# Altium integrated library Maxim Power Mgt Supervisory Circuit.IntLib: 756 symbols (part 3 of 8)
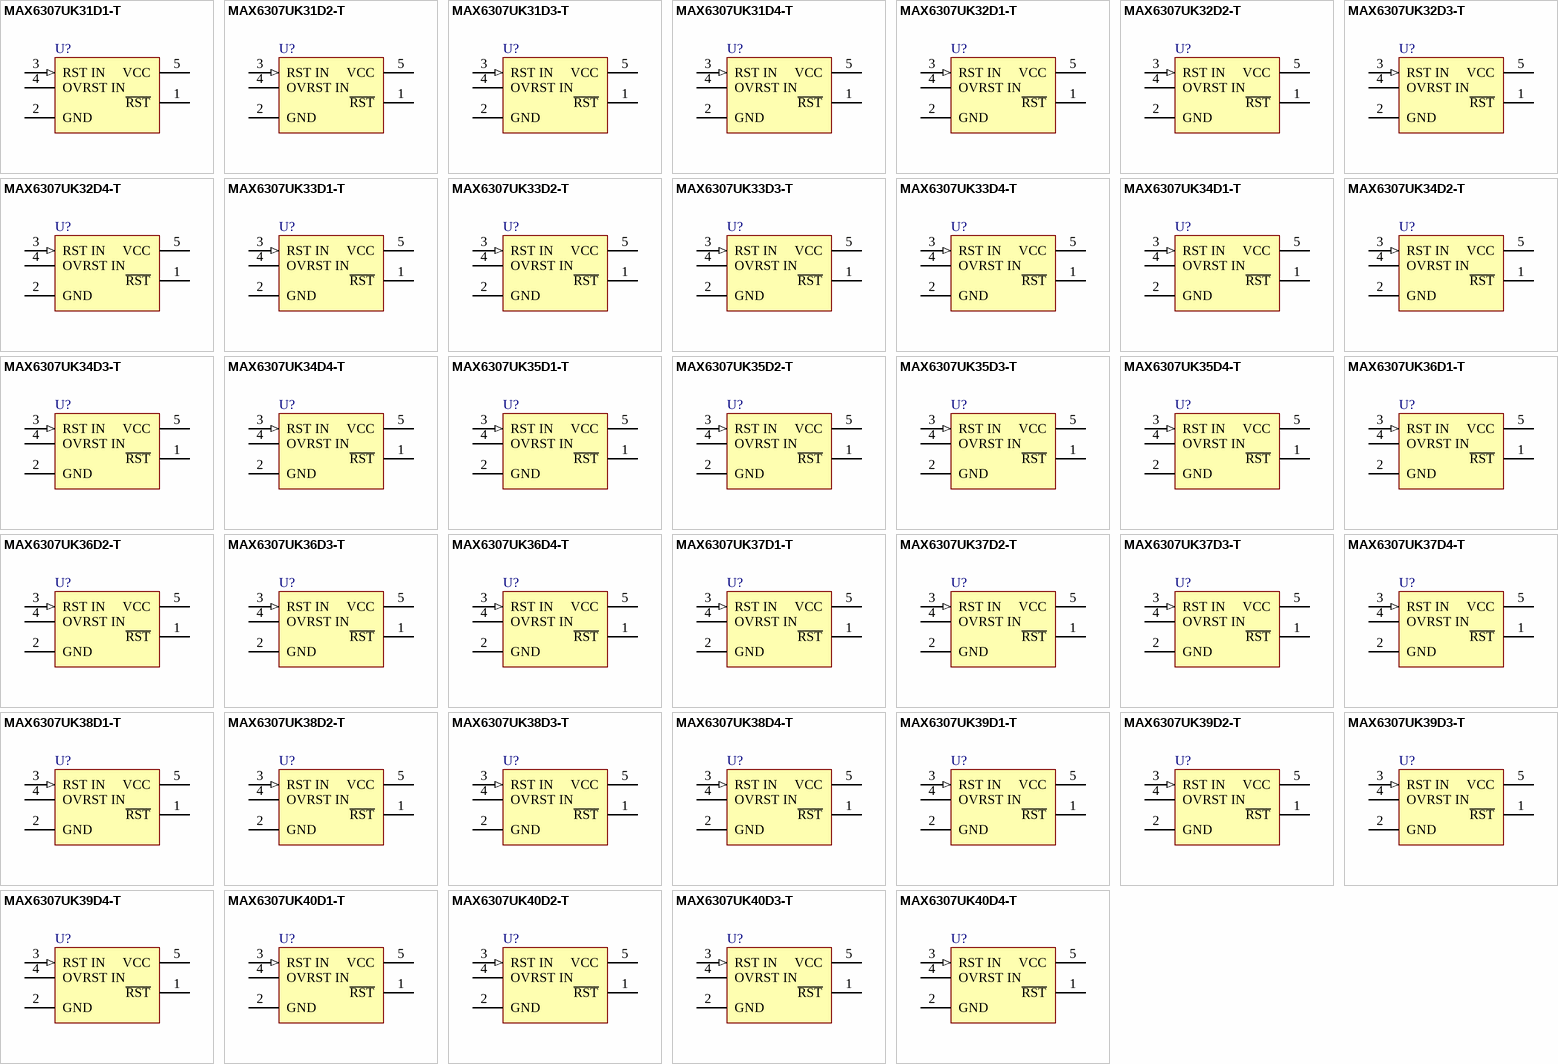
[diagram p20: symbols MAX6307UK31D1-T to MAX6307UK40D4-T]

## MAX6307UK35D3-T
designator U?
5-Pin, Multiple-Input, Programmable Reset IC
footprint SOT23-5_N (SOT23, 5-Leads, Body 2.9x1.6mm, Pitch 0.95mm, Lead Span 2.8mm, IPC Medium Density)
footprint SOT23-5_L (SOT23, 5-Leads, Body 2.9x1.6mm, Pitch 0.95mm, Lead Span 2.8mm, IPC High Density)
footprint SOT23-5_M (SOT23, 5-Leads, Body 2.9x1.6mm, Pitch 0.95mm, Lead Span 2.8mm, IPC Low Density)
pins: 1 ~{RST} (oc), 2 GND (power), 3 RST IN (in), 4 OVRST IN, 5 VCC (power)

## MAX6307UK35D4-T
designator U?
5-Pin, Multiple-Input, Programmable Reset IC
footprint SOT23-5_N (SOT23, 5-Leads, Body 2.9x1.6mm, Pitch 0.95mm, Lead Span 2.8mm, IPC Medium Density)
footprint SOT23-5_L (SOT23, 5-Leads, Body 2.9x1.6mm, Pitch 0.95mm, Lead Span 2.8mm, IPC High Density)
footprint SOT23-5_M (SOT23, 5-Leads, Body 2.9x1.6mm, Pitch 0.95mm, Lead Span 2.8mm, IPC Low Density)
pins: 1 ~{RST} (oc), 2 GND (power), 3 RST IN (in), 4 OVRST IN, 5 VCC (power)

## MAX6307UK36D1-T
designator U?
5-Pin, Multiple-Input, Programmable Reset IC
footprint SOT23-5_N (SOT23, 5-Leads, Body 2.9x1.6mm, Pitch 0.95mm, Lead Span 2.8mm, IPC Medium Density)
footprint SOT23-5_L (SOT23, 5-Leads, Body 2.9x1.6mm, Pitch 0.95mm, Lead Span 2.8mm, IPC High Density)
footprint SOT23-5_M (SOT23, 5-Leads, Body 2.9x1.6mm, Pitch 0.95mm, Lead Span 2.8mm, IPC Low Density)
pins: 1 ~{RST} (oc), 2 GND (power), 3 RST IN (in), 4 OVRST IN, 5 VCC (power)

## MAX6307UK36D2-T
designator U?
5-Pin, Multiple-Input, Programmable Reset IC
footprint SOT23-5_N (SOT23, 5-Leads, Body 2.9x1.6mm, Pitch 0.95mm, Lead Span 2.8mm, IPC Medium Density)
footprint SOT23-5_L (SOT23, 5-Leads, Body 2.9x1.6mm, Pitch 0.95mm, Lead Span 2.8mm, IPC High Density)
footprint SOT23-5_M (SOT23, 5-Leads, Body 2.9x1.6mm, Pitch 0.95mm, Lead Span 2.8mm, IPC Low Density)
pins: 1 ~{RST} (oc), 2 GND (power), 3 RST IN (in), 4 OVRST IN, 5 VCC (power)

## MAX6307UK36D3-T
designator U?
5-Pin, Multiple-Input, Programmable Reset IC
footprint SOT23-5_N (SOT23, 5-Leads, Body 2.9x1.6mm, Pitch 0.95mm, Lead Span 2.8mm, IPC Medium Density)
footprint SOT23-5_L (SOT23, 5-Leads, Body 2.9x1.6mm, Pitch 0.95mm, Lead Span 2.8mm, IPC High Density)
footprint SOT23-5_M (SOT23, 5-Leads, Body 2.9x1.6mm, Pitch 0.95mm, Lead Span 2.8mm, IPC Low Density)
pins: 1 ~{RST} (oc), 2 GND (power), 3 RST IN (in), 4 OVRST IN, 5 VCC (power)

## MAX6307UK36D4-T
designator U?
5-Pin, Multiple-Input, Programmable Reset IC
footprint SOT23-5_N (SOT23, 5-Leads, Body 2.9x1.6mm, Pitch 0.95mm, Lead Span 2.8mm, IPC Medium Density)
footprint SOT23-5_L (SOT23, 5-Leads, Body 2.9x1.6mm, Pitch 0.95mm, Lead Span 2.8mm, IPC High Density)
footprint SOT23-5_M (SOT23, 5-Leads, Body 2.9x1.6mm, Pitch 0.95mm, Lead Span 2.8mm, IPC Low Density)
pins: 1 ~{RST} (oc), 2 GND (power), 3 RST IN (in), 4 OVRST IN, 5 VCC (power)

## MAX6307UK37D1-T
designator U?
5-Pin, Multiple-Input, Programmable Reset IC
footprint SOT23-5_N (SOT23, 5-Leads, Body 2.9x1.6mm, Pitch 0.95mm, Lead Span 2.8mm, IPC Medium Density)
footprint SOT23-5_L (SOT23, 5-Leads, Body 2.9x1.6mm, Pitch 0.95mm, Lead Span 2.8mm, IPC High Density)
footprint SOT23-5_M (SOT23, 5-Leads, Body 2.9x1.6mm, Pitch 0.95mm, Lead Span 2.8mm, IPC Low Density)
pins: 1 ~{RST} (oc), 2 GND (power), 3 RST IN (in), 4 OVRST IN, 5 VCC (power)

## MAX6307UK37D2-T
designator U?
5-Pin, Multiple-Input, Programmable Reset IC
footprint SOT23-5_N (SOT23, 5-Leads, Body 2.9x1.6mm, Pitch 0.95mm, Lead Span 2.8mm, IPC Medium Density)
footprint SOT23-5_L (SOT23, 5-Leads, Body 2.9x1.6mm, Pitch 0.95mm, Lead Span 2.8mm, IPC High Density)
footprint SOT23-5_M (SOT23, 5-Leads, Body 2.9x1.6mm, Pitch 0.95mm, Lead Span 2.8mm, IPC Low Density)
pins: 1 ~{RST} (oc), 2 GND (power), 3 RST IN (in), 4 OVRST IN, 5 VCC (power)

## MAX6307UK37D3-T
designator U?
5-Pin, Multiple-Input, Programmable Reset IC
footprint SOT23-5_N (SOT23, 5-Leads, Body 2.9x1.6mm, Pitch 0.95mm, Lead Span 2.8mm, IPC Medium Density)
footprint SOT23-5_L (SOT23, 5-Leads, Body 2.9x1.6mm, Pitch 0.95mm, Lead Span 2.8mm, IPC High Density)
footprint SOT23-5_M (SOT23, 5-Leads, Body 2.9x1.6mm, Pitch 0.95mm, Lead Span 2.8mm, IPC Low Density)
pins: 1 ~{RST} (oc), 2 GND (power), 3 RST IN (in), 4 OVRST IN, 5 VCC (power)

## MAX6307UK37D4-T
designator U?
5-Pin, Multiple-Input, Programmable Reset IC
footprint SOT23-5_N (SOT23, 5-Leads, Body 2.9x1.6mm, Pitch 0.95mm, Lead Span 2.8mm, IPC Medium Density)
footprint SOT23-5_L (SOT23, 5-Leads, Body 2.9x1.6mm, Pitch 0.95mm, Lead Span 2.8mm, IPC High Density)
footprint SOT23-5_M (SOT23, 5-Leads, Body 2.9x1.6mm, Pitch 0.95mm, Lead Span 2.8mm, IPC Low Density)
pins: 1 ~{RST} (oc), 2 GND (power), 3 RST IN (in), 4 OVRST IN, 5 VCC (power)

## MAX6307UK38D1-T
designator U?
5-Pin, Multiple-Input, Programmable Reset IC
footprint SOT23-5_N (SOT23, 5-Leads, Body 2.9x1.6mm, Pitch 0.95mm, Lead Span 2.8mm, IPC Medium Density)
footprint SOT23-5_L (SOT23, 5-Leads, Body 2.9x1.6mm, Pitch 0.95mm, Lead Span 2.8mm, IPC High Density)
footprint SOT23-5_M (SOT23, 5-Leads, Body 2.9x1.6mm, Pitch 0.95mm, Lead Span 2.8mm, IPC Low Density)
pins: 1 ~{RST} (oc), 2 GND (power), 3 RST IN (in), 4 OVRST IN, 5 VCC (power)

## MAX6307UK38D2-T
designator U?
5-Pin, Multiple-Input, Programmable Reset IC
footprint SOT23-5_N (SOT23, 5-Leads, Body 2.9x1.6mm, Pitch 0.95mm, Lead Span 2.8mm, IPC Medium Density)
footprint SOT23-5_L (SOT23, 5-Leads, Body 2.9x1.6mm, Pitch 0.95mm, Lead Span 2.8mm, IPC High Density)
footprint SOT23-5_M (SOT23, 5-Leads, Body 2.9x1.6mm, Pitch 0.95mm, Lead Span 2.8mm, IPC Low Density)
pins: 1 ~{RST} (oc), 2 GND (power), 3 RST IN (in), 4 OVRST IN, 5 VCC (power)

## MAX6307UK38D3-T
designator U?
5-Pin, Multiple-Input, Programmable Reset IC
footprint SOT23-5_N (SOT23, 5-Leads, Body 2.9x1.6mm, Pitch 0.95mm, Lead Span 2.8mm, IPC Medium Density)
footprint SOT23-5_L (SOT23, 5-Leads, Body 2.9x1.6mm, Pitch 0.95mm, Lead Span 2.8mm, IPC High Density)
footprint SOT23-5_M (SOT23, 5-Leads, Body 2.9x1.6mm, Pitch 0.95mm, Lead Span 2.8mm, IPC Low Density)
pins: 1 ~{RST} (oc), 2 GND (power), 3 RST IN (in), 4 OVRST IN, 5 VCC (power)

## MAX6307UK38D4-T
designator U?
5-Pin, Multiple-Input, Programmable Reset IC
footprint SOT23-5_N (SOT23, 5-Leads, Body 2.9x1.6mm, Pitch 0.95mm, Lead Span 2.8mm, IPC Medium Density)
footprint SOT23-5_L (SOT23, 5-Leads, Body 2.9x1.6mm, Pitch 0.95mm, Lead Span 2.8mm, IPC High Density)
footprint SOT23-5_M (SOT23, 5-Leads, Body 2.9x1.6mm, Pitch 0.95mm, Lead Span 2.8mm, IPC Low Density)
pins: 1 ~{RST} (oc), 2 GND (power), 3 RST IN (in), 4 OVRST IN, 5 VCC (power)

## MAX6307UK39D1-T
designator U?
5-Pin, Multiple-Input, Programmable Reset IC
footprint SOT23-5_N (SOT23, 5-Leads, Body 2.9x1.6mm, Pitch 0.95mm, Lead Span 2.8mm, IPC Medium Density)
footprint SOT23-5_L (SOT23, 5-Leads, Body 2.9x1.6mm, Pitch 0.95mm, Lead Span 2.8mm, IPC High Density)
footprint SOT23-5_M (SOT23, 5-Leads, Body 2.9x1.6mm, Pitch 0.95mm, Lead Span 2.8mm, IPC Low Density)
pins: 1 ~{RST} (oc), 2 GND (power), 3 RST IN (in), 4 OVRST IN, 5 VCC (power)

## MAX6307UK39D2-T
designator U?
5-Pin, Multiple-Input, Programmable Reset IC
footprint SOT23-5_N (SOT23, 5-Leads, Body 2.9x1.6mm, Pitch 0.95mm, Lead Span 2.8mm, IPC Medium Density)
footprint SOT23-5_L (SOT23, 5-Leads, Body 2.9x1.6mm, Pitch 0.95mm, Lead Span 2.8mm, IPC High Density)
footprint SOT23-5_M (SOT23, 5-Leads, Body 2.9x1.6mm, Pitch 0.95mm, Lead Span 2.8mm, IPC Low Density)
pins: 1 ~{RST} (oc), 2 GND (power), 3 RST IN (in), 4 OVRST IN, 5 VCC (power)

## MAX6307UK39D3-T
designator U?
5-Pin, Multiple-Input, Programmable Reset IC
footprint SOT23-5_N (SOT23, 5-Leads, Body 2.9x1.6mm, Pitch 0.95mm, Lead Span 2.8mm, IPC Medium Density)
footprint SOT23-5_L (SOT23, 5-Leads, Body 2.9x1.6mm, Pitch 0.95mm, Lead Span 2.8mm, IPC High Density)
footprint SOT23-5_M (SOT23, 5-Leads, Body 2.9x1.6mm, Pitch 0.95mm, Lead Span 2.8mm, IPC Low Density)
pins: 1 ~{RST} (oc), 2 GND (power), 3 RST IN (in), 4 OVRST IN, 5 VCC (power)

## MAX6307UK39D4-T
designator U?
5-Pin, Multiple-Input, Programmable Reset IC
footprint SOT23-5_N (SOT23, 5-Leads, Body 2.9x1.6mm, Pitch 0.95mm, Lead Span 2.8mm, IPC Medium Density)
footprint SOT23-5_L (SOT23, 5-Leads, Body 2.9x1.6mm, Pitch 0.95mm, Lead Span 2.8mm, IPC High Density)
footprint SOT23-5_M (SOT23, 5-Leads, Body 2.9x1.6mm, Pitch 0.95mm, Lead Span 2.8mm, IPC Low Density)
pins: 1 ~{RST} (oc), 2 GND (power), 3 RST IN (in), 4 OVRST IN, 5 VCC (power)

## MAX6307UK40D1-T
designator U?
5-Pin, Multiple-Input, Programmable Reset IC
footprint SOT23-5_N (SOT23, 5-Leads, Body 2.9x1.6mm, Pitch 0.95mm, Lead Span 2.8mm, IPC Medium Density)
footprint SOT23-5_L (SOT23, 5-Leads, Body 2.9x1.6mm, Pitch 0.95mm, Lead Span 2.8mm, IPC High Density)
footprint SOT23-5_M (SOT23, 5-Leads, Body 2.9x1.6mm, Pitch 0.95mm, Lead Span 2.8mm, IPC Low Density)
pins: 1 ~{RST} (oc), 2 GND (power), 3 RST IN (in), 4 OVRST IN, 5 VCC (power)

## MAX6307UK40D2-T
designator U?
5-Pin, Multiple-Input, Programmable Reset IC
footprint SOT23-5_N (SOT23, 5-Leads, Body 2.9x1.6mm, Pitch 0.95mm, Lead Span 2.8mm, IPC Medium Density)
footprint SOT23-5_L (SOT23, 5-Leads, Body 2.9x1.6mm, Pitch 0.95mm, Lead Span 2.8mm, IPC High Density)
footprint SOT23-5_M (SOT23, 5-Leads, Body 2.9x1.6mm, Pitch 0.95mm, Lead Span 2.8mm, IPC Low Density)
pins: 1 ~{RST} (oc), 2 GND (power), 3 RST IN (in), 4 OVRST IN, 5 VCC (power)

## MAX6307UK40D3-T
designator U?
5-Pin, Multiple-Input, Programmable Reset IC
footprint SOT23-5_N (SOT23, 5-Leads, Body 2.9x1.6mm, Pitch 0.95mm, Lead Span 2.8mm, IPC Medium Density)
footprint SOT23-5_L (SOT23, 5-Leads, Body 2.9x1.6mm, Pitch 0.95mm, Lead Span 2.8mm, IPC High Density)
footprint SOT23-5_M (SOT23, 5-Leads, Body 2.9x1.6mm, Pitch 0.95mm, Lead Span 2.8mm, IPC Low Density)
pins: 1 ~{RST} (oc), 2 GND (power), 3 RST IN (in), 4 OVRST IN, 5 VCC (power)

## MAX6307UK40D4-T
designator U?
5-Pin, Multiple-Input, Programmable Reset IC
footprint SOT23-5_N (SOT23, 5-Leads, Body 2.9x1.6mm, Pitch 0.95mm, Lead Span 2.8mm, IPC Medium Density)
footprint SOT23-5_L (SOT23, 5-Leads, Body 2.9x1.6mm, Pitch 0.95mm, Lead Span 2.8mm, IPC High Density)
footprint SOT23-5_M (SOT23, 5-Leads, Body 2.9x1.6mm, Pitch 0.95mm, Lead Span 2.8mm, IPC Low Density)
pins: 1 ~{RST} (oc), 2 GND (power), 3 RST IN (in), 4 OVRST IN, 5 VCC (power)

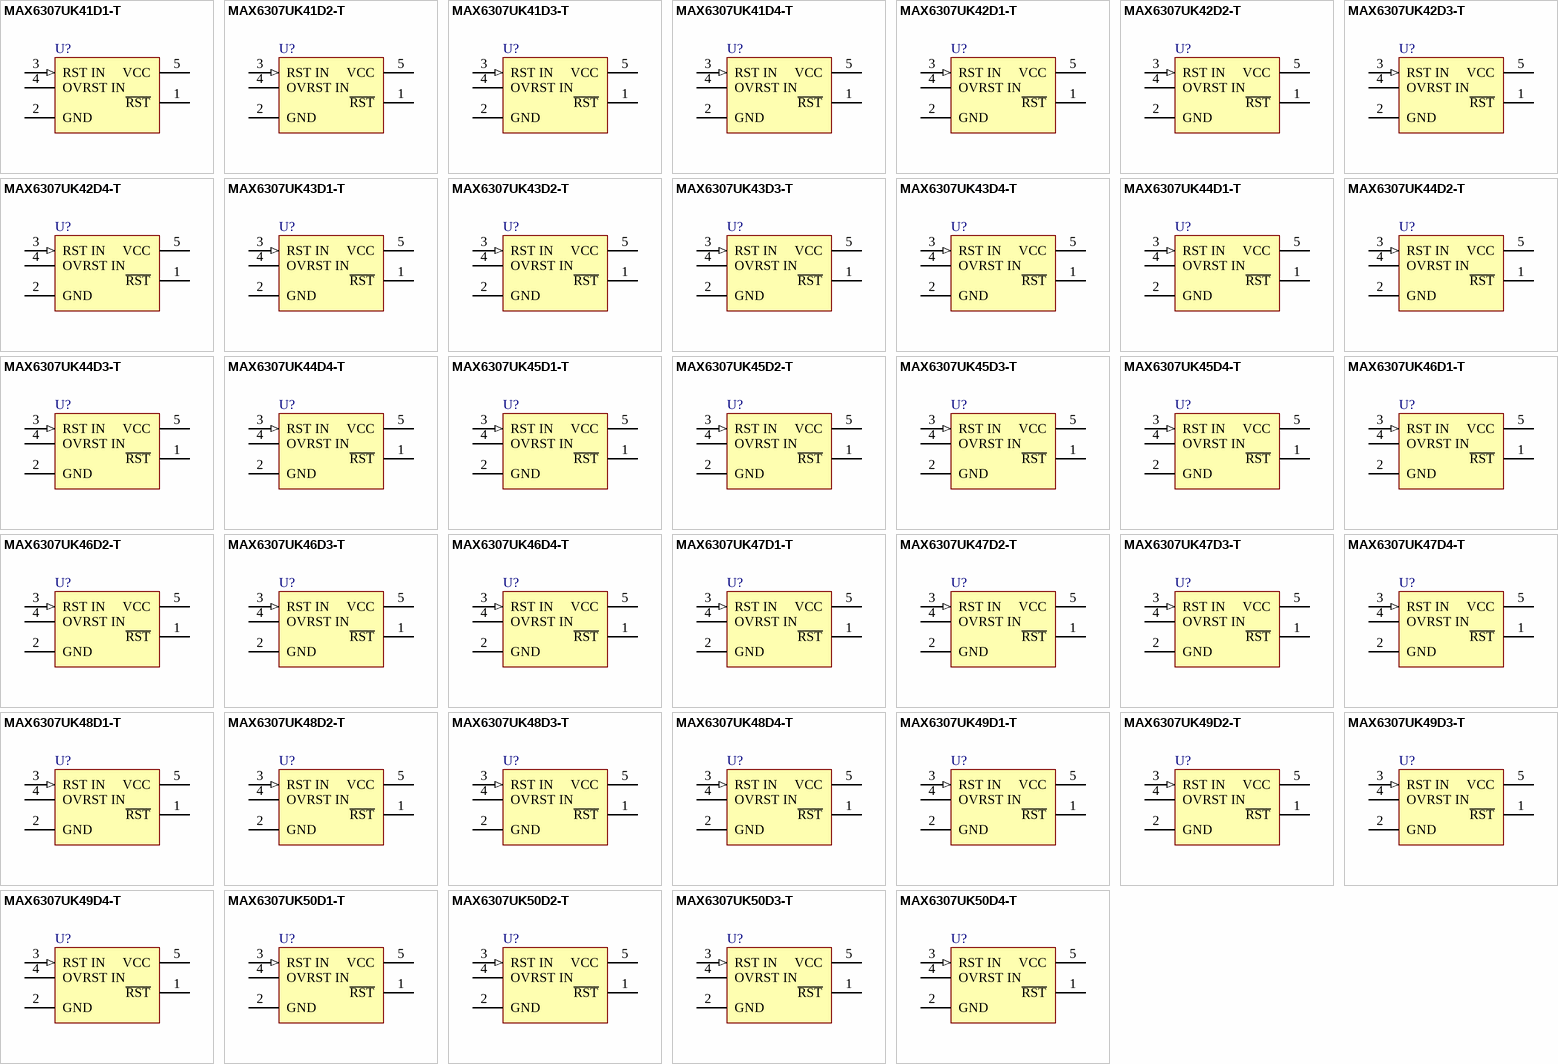
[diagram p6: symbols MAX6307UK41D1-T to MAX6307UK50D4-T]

## MAX6307UK41D1-T
designator U?
5-Pin, Multiple-Input, Programmable Reset IC
footprint SOT23-5_N (SOT23, 5-Leads, Body 2.9x1.6mm, Pitch 0.95mm, Lead Span 2.8mm, IPC Medium Density)
footprint SOT23-5_L (SOT23, 5-Leads, Body 2.9x1.6mm, Pitch 0.95mm, Lead Span 2.8mm, IPC High Density)
footprint SOT23-5_M (SOT23, 5-Leads, Body 2.9x1.6mm, Pitch 0.95mm, Lead Span 2.8mm, IPC Low Density)
pins: 1 ~{RST} (oc), 2 GND (power), 3 RST IN (in), 4 OVRST IN, 5 VCC (power)

## MAX6307UK41D2-T
designator U?
5-Pin, Multiple-Input, Programmable Reset IC
footprint SOT23-5_N (SOT23, 5-Leads, Body 2.9x1.6mm, Pitch 0.95mm, Lead Span 2.8mm, IPC Medium Density)
footprint SOT23-5_L (SOT23, 5-Leads, Body 2.9x1.6mm, Pitch 0.95mm, Lead Span 2.8mm, IPC High Density)
footprint SOT23-5_M (SOT23, 5-Leads, Body 2.9x1.6mm, Pitch 0.95mm, Lead Span 2.8mm, IPC Low Density)
pins: 1 ~{RST} (oc), 2 GND (power), 3 RST IN (in), 4 OVRST IN, 5 VCC (power)

## MAX6307UK41D3-T
designator U?
5-Pin, Multiple-Input, Programmable Reset IC
footprint SOT23-5_N (SOT23, 5-Leads, Body 2.9x1.6mm, Pitch 0.95mm, Lead Span 2.8mm, IPC Medium Density)
footprint SOT23-5_L (SOT23, 5-Leads, Body 2.9x1.6mm, Pitch 0.95mm, Lead Span 2.8mm, IPC High Density)
footprint SOT23-5_M (SOT23, 5-Leads, Body 2.9x1.6mm, Pitch 0.95mm, Lead Span 2.8mm, IPC Low Density)
pins: 1 ~{RST} (oc), 2 GND (power), 3 RST IN (in), 4 OVRST IN, 5 VCC (power)

## MAX6307UK41D4-T
designator U?
5-Pin, Multiple-Input, Programmable Reset IC
footprint SOT23-5_N (SOT23, 5-Leads, Body 2.9x1.6mm, Pitch 0.95mm, Lead Span 2.8mm, IPC Medium Density)
footprint SOT23-5_L (SOT23, 5-Leads, Body 2.9x1.6mm, Pitch 0.95mm, Lead Span 2.8mm, IPC High Density)
footprint SOT23-5_M (SOT23, 5-Leads, Body 2.9x1.6mm, Pitch 0.95mm, Lead Span 2.8mm, IPC Low Density)
pins: 1 ~{RST} (oc), 2 GND (power), 3 RST IN (in), 4 OVRST IN, 5 VCC (power)

## MAX6307UK42D1-T
designator U?
5-Pin, Multiple-Input, Programmable Reset IC
footprint SOT23-5_N (SOT23, 5-Leads, Body 2.9x1.6mm, Pitch 0.95mm, Lead Span 2.8mm, IPC Medium Density)
footprint SOT23-5_L (SOT23, 5-Leads, Body 2.9x1.6mm, Pitch 0.95mm, Lead Span 2.8mm, IPC High Density)
footprint SOT23-5_M (SOT23, 5-Leads, Body 2.9x1.6mm, Pitch 0.95mm, Lead Span 2.8mm, IPC Low Density)
pins: 1 ~{RST} (oc), 2 GND (power), 3 RST IN (in), 4 OVRST IN, 5 VCC (power)

## MAX6307UK42D2-T
designator U?
5-Pin, Multiple-Input, Programmable Reset IC
footprint SOT23-5_N (SOT23, 5-Leads, Body 2.9x1.6mm, Pitch 0.95mm, Lead Span 2.8mm, IPC Medium Density)
footprint SOT23-5_L (SOT23, 5-Leads, Body 2.9x1.6mm, Pitch 0.95mm, Lead Span 2.8mm, IPC High Density)
footprint SOT23-5_M (SOT23, 5-Leads, Body 2.9x1.6mm, Pitch 0.95mm, Lead Span 2.8mm, IPC Low Density)
pins: 1 ~{RST} (oc), 2 GND (power), 3 RST IN (in), 4 OVRST IN, 5 VCC (power)

## MAX6307UK42D3-T
designator U?
5-Pin, Multiple-Input, Programmable Reset IC
footprint SOT23-5_N (SOT23, 5-Leads, Body 2.9x1.6mm, Pitch 0.95mm, Lead Span 2.8mm, IPC Medium Density)
footprint SOT23-5_L (SOT23, 5-Leads, Body 2.9x1.6mm, Pitch 0.95mm, Lead Span 2.8mm, IPC High Density)
footprint SOT23-5_M (SOT23, 5-Leads, Body 2.9x1.6mm, Pitch 0.95mm, Lead Span 2.8mm, IPC Low Density)
pins: 1 ~{RST} (oc), 2 GND (power), 3 RST IN (in), 4 OVRST IN, 5 VCC (power)

## MAX6307UK42D4-T
designator U?
5-Pin, Multiple-Input, Programmable Reset IC
footprint SOT23-5_N (SOT23, 5-Leads, Body 2.9x1.6mm, Pitch 0.95mm, Lead Span 2.8mm, IPC Medium Density)
footprint SOT23-5_L (SOT23, 5-Leads, Body 2.9x1.6mm, Pitch 0.95mm, Lead Span 2.8mm, IPC High Density)
footprint SOT23-5_M (SOT23, 5-Leads, Body 2.9x1.6mm, Pitch 0.95mm, Lead Span 2.8mm, IPC Low Density)
pins: 1 ~{RST} (oc), 2 GND (power), 3 RST IN (in), 4 OVRST IN, 5 VCC (power)

## MAX6307UK43D1-T
designator U?
5-Pin, Multiple-Input, Programmable Reset IC
footprint SOT23-5_N (SOT23, 5-Leads, Body 2.9x1.6mm, Pitch 0.95mm, Lead Span 2.8mm, IPC Medium Density)
footprint SOT23-5_L (SOT23, 5-Leads, Body 2.9x1.6mm, Pitch 0.95mm, Lead Span 2.8mm, IPC High Density)
footprint SOT23-5_M (SOT23, 5-Leads, Body 2.9x1.6mm, Pitch 0.95mm, Lead Span 2.8mm, IPC Low Density)
pins: 1 ~{RST} (oc), 2 GND (power), 3 RST IN (in), 4 OVRST IN, 5 VCC (power)

## MAX6307UK43D2-T
designator U?
5-Pin, Multiple-Input, Programmable Reset IC
footprint SOT23-5_N (SOT23, 5-Leads, Body 2.9x1.6mm, Pitch 0.95mm, Lead Span 2.8mm, IPC Medium Density)
footprint SOT23-5_L (SOT23, 5-Leads, Body 2.9x1.6mm, Pitch 0.95mm, Lead Span 2.8mm, IPC High Density)
footprint SOT23-5_M (SOT23, 5-Leads, Body 2.9x1.6mm, Pitch 0.95mm, Lead Span 2.8mm, IPC Low Density)
pins: 1 ~{RST} (oc), 2 GND (power), 3 RST IN (in), 4 OVRST IN, 5 VCC (power)

## MAX6307UK43D3-T
designator U?
5-Pin, Multiple-Input, Programmable Reset IC
footprint SOT23-5_N (SOT23, 5-Leads, Body 2.9x1.6mm, Pitch 0.95mm, Lead Span 2.8mm, IPC Medium Density)
footprint SOT23-5_L (SOT23, 5-Leads, Body 2.9x1.6mm, Pitch 0.95mm, Lead Span 2.8mm, IPC High Density)
footprint SOT23-5_M (SOT23, 5-Leads, Body 2.9x1.6mm, Pitch 0.95mm, Lead Span 2.8mm, IPC Low Density)
pins: 1 ~{RST} (oc), 2 GND (power), 3 RST IN (in), 4 OVRST IN, 5 VCC (power)

## MAX6307UK43D4-T
designator U?
5-Pin, Multiple-Input, Programmable Reset IC
footprint SOT23-5_N (SOT23, 5-Leads, Body 2.9x1.6mm, Pitch 0.95mm, Lead Span 2.8mm, IPC Medium Density)
footprint SOT23-5_L (SOT23, 5-Leads, Body 2.9x1.6mm, Pitch 0.95mm, Lead Span 2.8mm, IPC High Density)
footprint SOT23-5_M (SOT23, 5-Leads, Body 2.9x1.6mm, Pitch 0.95mm, Lead Span 2.8mm, IPC Low Density)
pins: 1 ~{RST} (oc), 2 GND (power), 3 RST IN (in), 4 OVRST IN, 5 VCC (power)

## MAX6307UK44D1-T
designator U?
5-Pin, Multiple-Input, Programmable Reset IC
footprint SOT23-5_N (SOT23, 5-Leads, Body 2.9x1.6mm, Pitch 0.95mm, Lead Span 2.8mm, IPC Medium Density)
footprint SOT23-5_L (SOT23, 5-Leads, Body 2.9x1.6mm, Pitch 0.95mm, Lead Span 2.8mm, IPC High Density)
footprint SOT23-5_M (SOT23, 5-Leads, Body 2.9x1.6mm, Pitch 0.95mm, Lead Span 2.8mm, IPC Low Density)
pins: 1 ~{RST} (oc), 2 GND (power), 3 RST IN (in), 4 OVRST IN, 5 VCC (power)

## MAX6307UK44D2-T
designator U?
5-Pin, Multiple-Input, Programmable Reset IC
footprint SOT23-5_N (SOT23, 5-Leads, Body 2.9x1.6mm, Pitch 0.95mm, Lead Span 2.8mm, IPC Medium Density)
footprint SOT23-5_L (SOT23, 5-Leads, Body 2.9x1.6mm, Pitch 0.95mm, Lead Span 2.8mm, IPC High Density)
footprint SOT23-5_M (SOT23, 5-Leads, Body 2.9x1.6mm, Pitch 0.95mm, Lead Span 2.8mm, IPC Low Density)
pins: 1 ~{RST} (oc), 2 GND (power), 3 RST IN (in), 4 OVRST IN, 5 VCC (power)

## MAX6307UK44D3-T
designator U?
5-Pin, Multiple-Input, Programmable Reset IC
footprint SOT23-5_N (SOT23, 5-Leads, Body 2.9x1.6mm, Pitch 0.95mm, Lead Span 2.8mm, IPC Medium Density)
footprint SOT23-5_L (SOT23, 5-Leads, Body 2.9x1.6mm, Pitch 0.95mm, Lead Span 2.8mm, IPC High Density)
footprint SOT23-5_M (SOT23, 5-Leads, Body 2.9x1.6mm, Pitch 0.95mm, Lead Span 2.8mm, IPC Low Density)
pins: 1 ~{RST} (oc), 2 GND (power), 3 RST IN (in), 4 OVRST IN, 5 VCC (power)

## MAX6307UK44D4-T
designator U?
5-Pin, Multiple-Input, Programmable Reset IC
footprint SOT23-5_N (SOT23, 5-Leads, Body 2.9x1.6mm, Pitch 0.95mm, Lead Span 2.8mm, IPC Medium Density)
footprint SOT23-5_L (SOT23, 5-Leads, Body 2.9x1.6mm, Pitch 0.95mm, Lead Span 2.8mm, IPC High Density)
footprint SOT23-5_M (SOT23, 5-Leads, Body 2.9x1.6mm, Pitch 0.95mm, Lead Span 2.8mm, IPC Low Density)
pins: 1 ~{RST} (oc), 2 GND (power), 3 RST IN (in), 4 OVRST IN, 5 VCC (power)

## MAX6307UK45D1-T
designator U?
5-Pin, Multiple-Input, Programmable Reset IC
footprint SOT23-5_N (SOT23, 5-Leads, Body 2.9x1.6mm, Pitch 0.95mm, Lead Span 2.8mm, IPC Medium Density)
footprint SOT23-5_L (SOT23, 5-Leads, Body 2.9x1.6mm, Pitch 0.95mm, Lead Span 2.8mm, IPC High Density)
footprint SOT23-5_M (SOT23, 5-Leads, Body 2.9x1.6mm, Pitch 0.95mm, Lead Span 2.8mm, IPC Low Density)
pins: 1 ~{RST} (oc), 2 GND (power), 3 RST IN (in), 4 OVRST IN, 5 VCC (power)

## MAX6307UK45D2-T
designator U?
5-Pin, Multiple-Input, Programmable Reset IC
footprint SOT23-5_N (SOT23, 5-Leads, Body 2.9x1.6mm, Pitch 0.95mm, Lead Span 2.8mm, IPC Medium Density)
footprint SOT23-5_L (SOT23, 5-Leads, Body 2.9x1.6mm, Pitch 0.95mm, Lead Span 2.8mm, IPC High Density)
footprint SOT23-5_M (SOT23, 5-Leads, Body 2.9x1.6mm, Pitch 0.95mm, Lead Span 2.8mm, IPC Low Density)
pins: 1 ~{RST} (oc), 2 GND (power), 3 RST IN (in), 4 OVRST IN, 5 VCC (power)

## MAX6307UK45D3-T
designator U?
5-Pin, Multiple-Input, Programmable Reset IC
footprint SOT23-5_N (SOT23, 5-Leads, Body 2.9x1.6mm, Pitch 0.95mm, Lead Span 2.8mm, IPC Medium Density)
footprint SOT23-5_L (SOT23, 5-Leads, Body 2.9x1.6mm, Pitch 0.95mm, Lead Span 2.8mm, IPC High Density)
footprint SOT23-5_M (SOT23, 5-Leads, Body 2.9x1.6mm, Pitch 0.95mm, Lead Span 2.8mm, IPC Low Density)
pins: 1 ~{RST} (oc), 2 GND (power), 3 RST IN (in), 4 OVRST IN, 5 VCC (power)

## MAX6307UK45D4-T
designator U?
5-Pin, Multiple-Input, Programmable Reset IC
footprint SOT23-5_N (SOT23, 5-Leads, Body 2.9x1.6mm, Pitch 0.95mm, Lead Span 2.8mm, IPC Medium Density)
footprint SOT23-5_L (SOT23, 5-Leads, Body 2.9x1.6mm, Pitch 0.95mm, Lead Span 2.8mm, IPC High Density)
footprint SOT23-5_M (SOT23, 5-Leads, Body 2.9x1.6mm, Pitch 0.95mm, Lead Span 2.8mm, IPC Low Density)
pins: 1 ~{RST} (oc), 2 GND (power), 3 RST IN (in), 4 OVRST IN, 5 VCC (power)

## MAX6307UK46D1-T
designator U?
5-Pin, Multiple-Input, Programmable Reset IC
footprint SOT23-5_N (SOT23, 5-Leads, Body 2.9x1.6mm, Pitch 0.95mm, Lead Span 2.8mm, IPC Medium Density)
footprint SOT23-5_L (SOT23, 5-Leads, Body 2.9x1.6mm, Pitch 0.95mm, Lead Span 2.8mm, IPC High Density)
footprint SOT23-5_M (SOT23, 5-Leads, Body 2.9x1.6mm, Pitch 0.95mm, Lead Span 2.8mm, IPC Low Density)
pins: 1 ~{RST} (oc), 2 GND (power), 3 RST IN (in), 4 OVRST IN, 5 VCC (power)

## MAX6307UK46D2-T
designator U?
5-Pin, Multiple-Input, Programmable Reset IC
footprint SOT23-5_N (SOT23, 5-Leads, Body 2.9x1.6mm, Pitch 0.95mm, Lead Span 2.8mm, IPC Medium Density)
footprint SOT23-5_L (SOT23, 5-Leads, Body 2.9x1.6mm, Pitch 0.95mm, Lead Span 2.8mm, IPC High Density)
footprint SOT23-5_M (SOT23, 5-Leads, Body 2.9x1.6mm, Pitch 0.95mm, Lead Span 2.8mm, IPC Low Density)
pins: 1 ~{RST} (oc), 2 GND (power), 3 RST IN (in), 4 OVRST IN, 5 VCC (power)

## MAX6307UK46D3-T
designator U?
5-Pin, Multiple-Input, Programmable Reset IC
footprint SOT23-5_N (SOT23, 5-Leads, Body 2.9x1.6mm, Pitch 0.95mm, Lead Span 2.8mm, IPC Medium Density)
footprint SOT23-5_L (SOT23, 5-Leads, Body 2.9x1.6mm, Pitch 0.95mm, Lead Span 2.8mm, IPC High Density)
footprint SOT23-5_M (SOT23, 5-Leads, Body 2.9x1.6mm, Pitch 0.95mm, Lead Span 2.8mm, IPC Low Density)
pins: 1 ~{RST} (oc), 2 GND (power), 3 RST IN (in), 4 OVRST IN, 5 VCC (power)

## MAX6307UK46D4-T
designator U?
5-Pin, Multiple-Input, Programmable Reset IC
footprint SOT23-5_N (SOT23, 5-Leads, Body 2.9x1.6mm, Pitch 0.95mm, Lead Span 2.8mm, IPC Medium Density)
footprint SOT23-5_L (SOT23, 5-Leads, Body 2.9x1.6mm, Pitch 0.95mm, Lead Span 2.8mm, IPC High Density)
footprint SOT23-5_M (SOT23, 5-Leads, Body 2.9x1.6mm, Pitch 0.95mm, Lead Span 2.8mm, IPC Low Density)
pins: 1 ~{RST} (oc), 2 GND (power), 3 RST IN (in), 4 OVRST IN, 5 VCC (power)

## MAX6307UK47D1-T
designator U?
5-Pin, Multiple-Input, Programmable Reset IC
footprint SOT23-5_N (SOT23, 5-Leads, Body 2.9x1.6mm, Pitch 0.95mm, Lead Span 2.8mm, IPC Medium Density)
footprint SOT23-5_L (SOT23, 5-Leads, Body 2.9x1.6mm, Pitch 0.95mm, Lead Span 2.8mm, IPC High Density)
footprint SOT23-5_M (SOT23, 5-Leads, Body 2.9x1.6mm, Pitch 0.95mm, Lead Span 2.8mm, IPC Low Density)
pins: 1 ~{RST} (oc), 2 GND (power), 3 RST IN (in), 4 OVRST IN, 5 VCC (power)

## MAX6307UK47D2-T
designator U?
5-Pin, Multiple-Input, Programmable Reset IC
footprint SOT23-5_N (SOT23, 5-Leads, Body 2.9x1.6mm, Pitch 0.95mm, Lead Span 2.8mm, IPC Medium Density)
footprint SOT23-5_L (SOT23, 5-Leads, Body 2.9x1.6mm, Pitch 0.95mm, Lead Span 2.8mm, IPC High Density)
footprint SOT23-5_M (SOT23, 5-Leads, Body 2.9x1.6mm, Pitch 0.95mm, Lead Span 2.8mm, IPC Low Density)
pins: 1 ~{RST} (oc), 2 GND (power), 3 RST IN (in), 4 OVRST IN, 5 VCC (power)

## MAX6307UK47D3-T
designator U?
5-Pin, Multiple-Input, Programmable Reset IC
footprint SOT23-5_N (SOT23, 5-Leads, Body 2.9x1.6mm, Pitch 0.95mm, Lead Span 2.8mm, IPC Medium Density)
footprint SOT23-5_L (SOT23, 5-Leads, Body 2.9x1.6mm, Pitch 0.95mm, Lead Span 2.8mm, IPC High Density)
footprint SOT23-5_M (SOT23, 5-Leads, Body 2.9x1.6mm, Pitch 0.95mm, Lead Span 2.8mm, IPC Low Density)
pins: 1 ~{RST} (oc), 2 GND (power), 3 RST IN (in), 4 OVRST IN, 5 VCC (power)

## MAX6307UK47D4-T
designator U?
5-Pin, Multiple-Input, Programmable Reset IC
footprint SOT23-5_N (SOT23, 5-Leads, Body 2.9x1.6mm, Pitch 0.95mm, Lead Span 2.8mm, IPC Medium Density)
footprint SOT23-5_L (SOT23, 5-Leads, Body 2.9x1.6mm, Pitch 0.95mm, Lead Span 2.8mm, IPC High Density)
footprint SOT23-5_M (SOT23, 5-Leads, Body 2.9x1.6mm, Pitch 0.95mm, Lead Span 2.8mm, IPC Low Density)
pins: 1 ~{RST} (oc), 2 GND (power), 3 RST IN (in), 4 OVRST IN, 5 VCC (power)

## MAX6307UK48D1-T
designator U?
5-Pin, Multiple-Input, Programmable Reset IC
footprint SOT23-5_N (SOT23, 5-Leads, Body 2.9x1.6mm, Pitch 0.95mm, Lead Span 2.8mm, IPC Medium Density)
footprint SOT23-5_L (SOT23, 5-Leads, Body 2.9x1.6mm, Pitch 0.95mm, Lead Span 2.8mm, IPC High Density)
footprint SOT23-5_M (SOT23, 5-Leads, Body 2.9x1.6mm, Pitch 0.95mm, Lead Span 2.8mm, IPC Low Density)
pins: 1 ~{RST} (oc), 2 GND (power), 3 RST IN (in), 4 OVRST IN, 5 VCC (power)

## MAX6307UK48D2-T
designator U?
5-Pin, Multiple-Input, Programmable Reset IC
footprint SOT23-5_N (SOT23, 5-Leads, Body 2.9x1.6mm, Pitch 0.95mm, Lead Span 2.8mm, IPC Medium Density)
footprint SOT23-5_L (SOT23, 5-Leads, Body 2.9x1.6mm, Pitch 0.95mm, Lead Span 2.8mm, IPC High Density)
footprint SOT23-5_M (SOT23, 5-Leads, Body 2.9x1.6mm, Pitch 0.95mm, Lead Span 2.8mm, IPC Low Density)
pins: 1 ~{RST} (oc), 2 GND (power), 3 RST IN (in), 4 OVRST IN, 5 VCC (power)

## MAX6307UK48D3-T
designator U?
5-Pin, Multiple-Input, Programmable Reset IC
footprint SOT23-5_N (SOT23, 5-Leads, Body 2.9x1.6mm, Pitch 0.95mm, Lead Span 2.8mm, IPC Medium Density)
footprint SOT23-5_L (SOT23, 5-Leads, Body 2.9x1.6mm, Pitch 0.95mm, Lead Span 2.8mm, IPC High Density)
footprint SOT23-5_M (SOT23, 5-Leads, Body 2.9x1.6mm, Pitch 0.95mm, Lead Span 2.8mm, IPC Low Density)
pins: 1 ~{RST} (oc), 2 GND (power), 3 RST IN (in), 4 OVRST IN, 5 VCC (power)

## MAX6307UK48D4-T
designator U?
5-Pin, Multiple-Input, Programmable Reset IC
footprint SOT23-5_N (SOT23, 5-Leads, Body 2.9x1.6mm, Pitch 0.95mm, Lead Span 2.8mm, IPC Medium Density)
footprint SOT23-5_L (SOT23, 5-Leads, Body 2.9x1.6mm, Pitch 0.95mm, Lead Span 2.8mm, IPC High Density)
footprint SOT23-5_M (SOT23, 5-Leads, Body 2.9x1.6mm, Pitch 0.95mm, Lead Span 2.8mm, IPC Low Density)
pins: 1 ~{RST} (oc), 2 GND (power), 3 RST IN (in), 4 OVRST IN, 5 VCC (power)

## MAX6307UK49D1-T
designator U?
5-Pin, Multiple-Input, Programmable Reset IC
footprint SOT23-5_N (SOT23, 5-Leads, Body 2.9x1.6mm, Pitch 0.95mm, Lead Span 2.8mm, IPC Medium Density)
footprint SOT23-5_L (SOT23, 5-Leads, Body 2.9x1.6mm, Pitch 0.95mm, Lead Span 2.8mm, IPC High Density)
footprint SOT23-5_M (SOT23, 5-Leads, Body 2.9x1.6mm, Pitch 0.95mm, Lead Span 2.8mm, IPC Low Density)
pins: 1 ~{RST} (oc), 2 GND (power), 3 RST IN (in), 4 OVRST IN, 5 VCC (power)

## MAX6307UK49D2-T
designator U?
5-Pin, Multiple-Input, Programmable Reset IC
footprint SOT23-5_N (SOT23, 5-Leads, Body 2.9x1.6mm, Pitch 0.95mm, Lead Span 2.8mm, IPC Medium Density)
footprint SOT23-5_L (SOT23, 5-Leads, Body 2.9x1.6mm, Pitch 0.95mm, Lead Span 2.8mm, IPC High Density)
footprint SOT23-5_M (SOT23, 5-Leads, Body 2.9x1.6mm, Pitch 0.95mm, Lead Span 2.8mm, IPC Low Density)
pins: 1 ~{RST} (oc), 2 GND (power), 3 RST IN (in), 4 OVRST IN, 5 VCC (power)

## MAX6307UK49D3-T
designator U?
5-Pin, Multiple-Input, Programmable Reset IC
footprint SOT23-5_N (SOT23, 5-Leads, Body 2.9x1.6mm, Pitch 0.95mm, Lead Span 2.8mm, IPC Medium Density)
footprint SOT23-5_L (SOT23, 5-Leads, Body 2.9x1.6mm, Pitch 0.95mm, Lead Span 2.8mm, IPC High Density)
footprint SOT23-5_M (SOT23, 5-Leads, Body 2.9x1.6mm, Pitch 0.95mm, Lead Span 2.8mm, IPC Low Density)
pins: 1 ~{RST} (oc), 2 GND (power), 3 RST IN (in), 4 OVRST IN, 5 VCC (power)

## MAX6307UK49D4-T
designator U?
5-Pin, Multiple-Input, Programmable Reset IC
footprint SOT23-5_N (SOT23, 5-Leads, Body 2.9x1.6mm, Pitch 0.95mm, Lead Span 2.8mm, IPC Medium Density)
footprint SOT23-5_L (SOT23, 5-Leads, Body 2.9x1.6mm, Pitch 0.95mm, Lead Span 2.8mm, IPC High Density)
footprint SOT23-5_M (SOT23, 5-Leads, Body 2.9x1.6mm, Pitch 0.95mm, Lead Span 2.8mm, IPC Low Density)
pins: 1 ~{RST} (oc), 2 GND (power), 3 RST IN (in), 4 OVRST IN, 5 VCC (power)

## MAX6307UK50D1-T
designator U?
5-Pin, Multiple-Input, Programmable Reset IC
footprint SOT23-5_N (SOT23, 5-Leads, Body 2.9x1.6mm, Pitch 0.95mm, Lead Span 2.8mm, IPC Medium Density)
footprint SOT23-5_L (SOT23, 5-Leads, Body 2.9x1.6mm, Pitch 0.95mm, Lead Span 2.8mm, IPC High Density)
footprint SOT23-5_M (SOT23, 5-Leads, Body 2.9x1.6mm, Pitch 0.95mm, Lead Span 2.8mm, IPC Low Density)
pins: 1 ~{RST} (oc), 2 GND (power), 3 RST IN (in), 4 OVRST IN, 5 VCC (power)

## MAX6307UK50D2-T
designator U?
5-Pin, Multiple-Input, Programmable Reset IC
footprint SOT23-5_N (SOT23, 5-Leads, Body 2.9x1.6mm, Pitch 0.95mm, Lead Span 2.8mm, IPC Medium Density)
footprint SOT23-5_L (SOT23, 5-Leads, Body 2.9x1.6mm, Pitch 0.95mm, Lead Span 2.8mm, IPC High Density)
footprint SOT23-5_M (SOT23, 5-Leads, Body 2.9x1.6mm, Pitch 0.95mm, Lead Span 2.8mm, IPC Low Density)
pins: 1 ~{RST} (oc), 2 GND (power), 3 RST IN (in), 4 OVRST IN, 5 VCC (power)

## MAX6307UK50D3-T
designator U?
5-Pin, Multiple-Input, Programmable Reset IC
footprint SOT23-5_N (SOT23, 5-Leads, Body 2.9x1.6mm, Pitch 0.95mm, Lead Span 2.8mm, IPC Medium Density)
footprint SOT23-5_L (SOT23, 5-Leads, Body 2.9x1.6mm, Pitch 0.95mm, Lead Span 2.8mm, IPC High Density)
footprint SOT23-5_M (SOT23, 5-Leads, Body 2.9x1.6mm, Pitch 0.95mm, Lead Span 2.8mm, IPC Low Density)
pins: 1 ~{RST} (oc), 2 GND (power), 3 RST IN (in), 4 OVRST IN, 5 VCC (power)

## MAX6307UK50D4-T
designator U?
5-Pin, Multiple-Input, Programmable Reset IC
footprint SOT23-5_N (SOT23, 5-Leads, Body 2.9x1.6mm, Pitch 0.95mm, Lead Span 2.8mm, IPC Medium Density)
footprint SOT23-5_L (SOT23, 5-Leads, Body 2.9x1.6mm, Pitch 0.95mm, Lead Span 2.8mm, IPC High Density)
footprint SOT23-5_M (SOT23, 5-Leads, Body 2.9x1.6mm, Pitch 0.95mm, Lead Span 2.8mm, IPC Low Density)
pins: 1 ~{RST} (oc), 2 GND (power), 3 RST IN (in), 4 OVRST IN, 5 VCC (power)

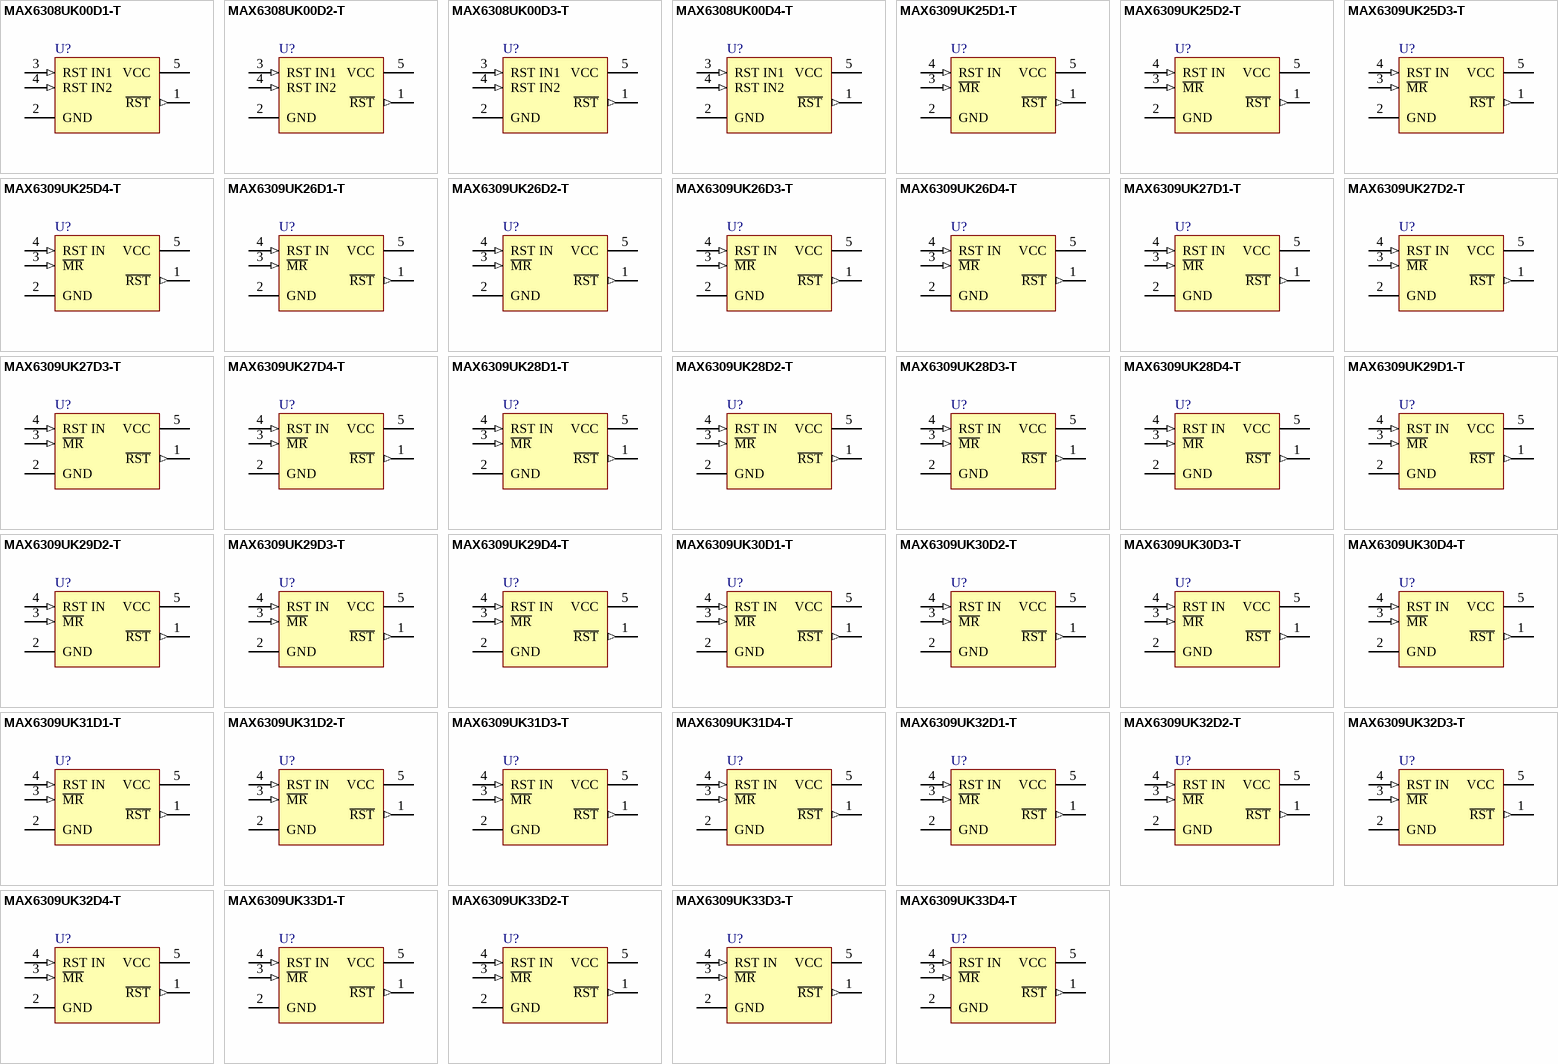
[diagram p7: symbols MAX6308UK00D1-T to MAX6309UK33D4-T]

## MAX6308UK00D1-T
designator U?
5-Pin, Multiple-Input, Programmable Reset IC
footprint SOT23-5_N (SOT23, 5-Leads, Body 2.9x1.6mm, Pitch 0.95mm, Lead Span 2.8mm, IPC Medium Density)
footprint SOT23-5_L (SOT23, 5-Leads, Body 2.9x1.6mm, Pitch 0.95mm, Lead Span 2.8mm, IPC High Density)
footprint SOT23-5_M (SOT23, 5-Leads, Body 2.9x1.6mm, Pitch 0.95mm, Lead Span 2.8mm, IPC Low Density)
pins: 1 ~{RST} (out), 2 GND (power), 3 RST IN1 (in), 4 RST IN2 (in), 5 VCC (power)

## MAX6308UK00D2-T
designator U?
5-Pin, Multiple-Input, Programmable Reset IC
footprint SOT23-5_N (SOT23, 5-Leads, Body 2.9x1.6mm, Pitch 0.95mm, Lead Span 2.8mm, IPC Medium Density)
footprint SOT23-5_L (SOT23, 5-Leads, Body 2.9x1.6mm, Pitch 0.95mm, Lead Span 2.8mm, IPC High Density)
footprint SOT23-5_M (SOT23, 5-Leads, Body 2.9x1.6mm, Pitch 0.95mm, Lead Span 2.8mm, IPC Low Density)
pins: 1 ~{RST} (out), 2 GND (power), 3 RST IN1 (in), 4 RST IN2 (in), 5 VCC (power)

## MAX6308UK00D3-T
designator U?
5-Pin, Multiple-Input, Programmable Reset IC
footprint SOT23-5_N (SOT23, 5-Leads, Body 2.9x1.6mm, Pitch 0.95mm, Lead Span 2.8mm, IPC Medium Density)
footprint SOT23-5_L (SOT23, 5-Leads, Body 2.9x1.6mm, Pitch 0.95mm, Lead Span 2.8mm, IPC High Density)
footprint SOT23-5_M (SOT23, 5-Leads, Body 2.9x1.6mm, Pitch 0.95mm, Lead Span 2.8mm, IPC Low Density)
pins: 1 ~{RST} (out), 2 GND (power), 3 RST IN1 (in), 4 RST IN2 (in), 5 VCC (power)

## MAX6308UK00D4-T
designator U?
5-Pin, Multiple-Input, Programmable Reset IC
footprint SOT23-5_N (SOT23, 5-Leads, Body 2.9x1.6mm, Pitch 0.95mm, Lead Span 2.8mm, IPC Medium Density)
footprint SOT23-5_L (SOT23, 5-Leads, Body 2.9x1.6mm, Pitch 0.95mm, Lead Span 2.8mm, IPC High Density)
footprint SOT23-5_M (SOT23, 5-Leads, Body 2.9x1.6mm, Pitch 0.95mm, Lead Span 2.8mm, IPC Low Density)
pins: 1 ~{RST} (out), 2 GND (power), 3 RST IN1 (in), 4 RST IN2 (in), 5 VCC (power)

## MAX6309UK25D1-T
designator U?
5-Pin, Multiple-Input, Programmable Reset IC
footprint SOT23-5_N (SOT23, 5-Leads, Body 2.9x1.6mm, Pitch 0.95mm, Lead Span 2.8mm, IPC Medium Density)
footprint SOT23-5_L (SOT23, 5-Leads, Body 2.9x1.6mm, Pitch 0.95mm, Lead Span 2.8mm, IPC High Density)
footprint SOT23-5_M (SOT23, 5-Leads, Body 2.9x1.6mm, Pitch 0.95mm, Lead Span 2.8mm, IPC Low Density)
pins: 1 ~{RST} (out), 2 GND (power), 3 ~{MR} (in), 4 RST IN (in), 5 VCC (power)

## MAX6309UK25D2-T
designator U?
5-Pin, Multiple-Input, Programmable Reset IC
footprint SOT23-5_N (SOT23, 5-Leads, Body 2.9x1.6mm, Pitch 0.95mm, Lead Span 2.8mm, IPC Medium Density)
footprint SOT23-5_L (SOT23, 5-Leads, Body 2.9x1.6mm, Pitch 0.95mm, Lead Span 2.8mm, IPC High Density)
footprint SOT23-5_M (SOT23, 5-Leads, Body 2.9x1.6mm, Pitch 0.95mm, Lead Span 2.8mm, IPC Low Density)
pins: 1 ~{RST} (out), 2 GND (power), 3 ~{MR} (in), 4 RST IN (in), 5 VCC (power)

## MAX6309UK25D3-T
designator U?
5-Pin, Multiple-Input, Programmable Reset IC
footprint SOT23-5_N (SOT23, 5-Leads, Body 2.9x1.6mm, Pitch 0.95mm, Lead Span 2.8mm, IPC Medium Density)
footprint SOT23-5_L (SOT23, 5-Leads, Body 2.9x1.6mm, Pitch 0.95mm, Lead Span 2.8mm, IPC High Density)
footprint SOT23-5_M (SOT23, 5-Leads, Body 2.9x1.6mm, Pitch 0.95mm, Lead Span 2.8mm, IPC Low Density)
pins: 1 ~{RST} (out), 2 GND (power), 3 ~{MR} (in), 4 RST IN (in), 5 VCC (power)

## MAX6309UK25D4-T
designator U?
5-Pin, Multiple-Input, Programmable Reset IC
footprint SOT23-5_N (SOT23, 5-Leads, Body 2.9x1.6mm, Pitch 0.95mm, Lead Span 2.8mm, IPC Medium Density)
footprint SOT23-5_L (SOT23, 5-Leads, Body 2.9x1.6mm, Pitch 0.95mm, Lead Span 2.8mm, IPC High Density)
footprint SOT23-5_M (SOT23, 5-Leads, Body 2.9x1.6mm, Pitch 0.95mm, Lead Span 2.8mm, IPC Low Density)
pins: 1 ~{RST} (out), 2 GND (power), 3 ~{MR} (in), 4 RST IN (in), 5 VCC (power)

## MAX6309UK26D1-T
designator U?
5-Pin, Multiple-Input, Programmable Reset IC
footprint SOT23-5_N (SOT23, 5-Leads, Body 2.9x1.6mm, Pitch 0.95mm, Lead Span 2.8mm, IPC Medium Density)
footprint SOT23-5_L (SOT23, 5-Leads, Body 2.9x1.6mm, Pitch 0.95mm, Lead Span 2.8mm, IPC High Density)
footprint SOT23-5_M (SOT23, 5-Leads, Body 2.9x1.6mm, Pitch 0.95mm, Lead Span 2.8mm, IPC Low Density)
pins: 1 ~{RST} (out), 2 GND (power), 3 ~{MR} (in), 4 RST IN (in), 5 VCC (power)

## MAX6309UK26D2-T
designator U?
5-Pin, Multiple-Input, Programmable Reset IC
footprint SOT23-5_N (SOT23, 5-Leads, Body 2.9x1.6mm, Pitch 0.95mm, Lead Span 2.8mm, IPC Medium Density)
footprint SOT23-5_L (SOT23, 5-Leads, Body 2.9x1.6mm, Pitch 0.95mm, Lead Span 2.8mm, IPC High Density)
footprint SOT23-5_M (SOT23, 5-Leads, Body 2.9x1.6mm, Pitch 0.95mm, Lead Span 2.8mm, IPC Low Density)
pins: 1 ~{RST} (out), 2 GND (power), 3 ~{MR} (in), 4 RST IN (in), 5 VCC (power)

## MAX6309UK26D3-T
designator U?
5-Pin, Multiple-Input, Programmable Reset IC
footprint SOT23-5_N (SOT23, 5-Leads, Body 2.9x1.6mm, Pitch 0.95mm, Lead Span 2.8mm, IPC Medium Density)
footprint SOT23-5_L (SOT23, 5-Leads, Body 2.9x1.6mm, Pitch 0.95mm, Lead Span 2.8mm, IPC High Density)
footprint SOT23-5_M (SOT23, 5-Leads, Body 2.9x1.6mm, Pitch 0.95mm, Lead Span 2.8mm, IPC Low Density)
pins: 1 ~{RST} (out), 2 GND (power), 3 ~{MR} (in), 4 RST IN (in), 5 VCC (power)

## MAX6309UK26D4-T
designator U?
5-Pin, Multiple-Input, Programmable Reset IC
footprint SOT23-5_N (SOT23, 5-Leads, Body 2.9x1.6mm, Pitch 0.95mm, Lead Span 2.8mm, IPC Medium Density)
footprint SOT23-5_L (SOT23, 5-Leads, Body 2.9x1.6mm, Pitch 0.95mm, Lead Span 2.8mm, IPC High Density)
footprint SOT23-5_M (SOT23, 5-Leads, Body 2.9x1.6mm, Pitch 0.95mm, Lead Span 2.8mm, IPC Low Density)
pins: 1 ~{RST} (out), 2 GND (power), 3 ~{MR} (in), 4 RST IN (in), 5 VCC (power)

## MAX6309UK27D1-T
designator U?
5-Pin, Multiple-Input, Programmable Reset IC
footprint SOT23-5_N (SOT23, 5-Leads, Body 2.9x1.6mm, Pitch 0.95mm, Lead Span 2.8mm, IPC Medium Density)
footprint SOT23-5_L (SOT23, 5-Leads, Body 2.9x1.6mm, Pitch 0.95mm, Lead Span 2.8mm, IPC High Density)
footprint SOT23-5_M (SOT23, 5-Leads, Body 2.9x1.6mm, Pitch 0.95mm, Lead Span 2.8mm, IPC Low Density)
pins: 1 ~{RST} (out), 2 GND (power), 3 ~{MR} (in), 4 RST IN (in), 5 VCC (power)

## MAX6309UK27D2-T
designator U?
5-Pin, Multiple-Input, Programmable Reset IC
footprint SOT23-5_N (SOT23, 5-Leads, Body 2.9x1.6mm, Pitch 0.95mm, Lead Span 2.8mm, IPC Medium Density)
footprint SOT23-5_L (SOT23, 5-Leads, Body 2.9x1.6mm, Pitch 0.95mm, Lead Span 2.8mm, IPC High Density)
footprint SOT23-5_M (SOT23, 5-Leads, Body 2.9x1.6mm, Pitch 0.95mm, Lead Span 2.8mm, IPC Low Density)
pins: 1 ~{RST} (out), 2 GND (power), 3 ~{MR} (in), 4 RST IN (in), 5 VCC (power)

## MAX6309UK27D3-T
designator U?
5-Pin, Multiple-Input, Programmable Reset IC
footprint SOT23-5_N (SOT23, 5-Leads, Body 2.9x1.6mm, Pitch 0.95mm, Lead Span 2.8mm, IPC Medium Density)
footprint SOT23-5_L (SOT23, 5-Leads, Body 2.9x1.6mm, Pitch 0.95mm, Lead Span 2.8mm, IPC High Density)
footprint SOT23-5_M (SOT23, 5-Leads, Body 2.9x1.6mm, Pitch 0.95mm, Lead Span 2.8mm, IPC Low Density)
pins: 1 ~{RST} (out), 2 GND (power), 3 ~{MR} (in), 4 RST IN (in), 5 VCC (power)

## MAX6309UK27D4-T
designator U?
5-Pin, Multiple-Input, Programmable Reset IC
footprint SOT23-5_N (SOT23, 5-Leads, Body 2.9x1.6mm, Pitch 0.95mm, Lead Span 2.8mm, IPC Medium Density)
footprint SOT23-5_L (SOT23, 5-Leads, Body 2.9x1.6mm, Pitch 0.95mm, Lead Span 2.8mm, IPC High Density)
footprint SOT23-5_M (SOT23, 5-Leads, Body 2.9x1.6mm, Pitch 0.95mm, Lead Span 2.8mm, IPC Low Density)
pins: 1 ~{RST} (out), 2 GND (power), 3 ~{MR} (in), 4 RST IN (in), 5 VCC (power)

## MAX6309UK28D1-T
designator U?
5-Pin, Multiple-Input, Programmable Reset IC
footprint SOT23-5_N (SOT23, 5-Leads, Body 2.9x1.6mm, Pitch 0.95mm, Lead Span 2.8mm, IPC Medium Density)
footprint SOT23-5_L (SOT23, 5-Leads, Body 2.9x1.6mm, Pitch 0.95mm, Lead Span 2.8mm, IPC High Density)
footprint SOT23-5_M (SOT23, 5-Leads, Body 2.9x1.6mm, Pitch 0.95mm, Lead Span 2.8mm, IPC Low Density)
pins: 1 ~{RST} (out), 2 GND (power), 3 ~{MR} (in), 4 RST IN (in), 5 VCC (power)

## MAX6309UK28D2-T
designator U?
5-Pin, Multiple-Input, Programmable Reset IC
footprint SOT23-5_N (SOT23, 5-Leads, Body 2.9x1.6mm, Pitch 0.95mm, Lead Span 2.8mm, IPC Medium Density)
footprint SOT23-5_L (SOT23, 5-Leads, Body 2.9x1.6mm, Pitch 0.95mm, Lead Span 2.8mm, IPC High Density)
footprint SOT23-5_M (SOT23, 5-Leads, Body 2.9x1.6mm, Pitch 0.95mm, Lead Span 2.8mm, IPC Low Density)
pins: 1 ~{RST} (out), 2 GND (power), 3 ~{MR} (in), 4 RST IN (in), 5 VCC (power)

## MAX6309UK28D3-T
designator U?
5-Pin, Multiple-Input, Programmable Reset IC
footprint SOT23-5_N (SOT23, 5-Leads, Body 2.9x1.6mm, Pitch 0.95mm, Lead Span 2.8mm, IPC Medium Density)
footprint SOT23-5_L (SOT23, 5-Leads, Body 2.9x1.6mm, Pitch 0.95mm, Lead Span 2.8mm, IPC High Density)
footprint SOT23-5_M (SOT23, 5-Leads, Body 2.9x1.6mm, Pitch 0.95mm, Lead Span 2.8mm, IPC Low Density)
pins: 1 ~{RST} (out), 2 GND (power), 3 ~{MR} (in), 4 RST IN (in), 5 VCC (power)

## MAX6309UK28D4-T
designator U?
5-Pin, Multiple-Input, Programmable Reset IC
footprint SOT23-5_N (SOT23, 5-Leads, Body 2.9x1.6mm, Pitch 0.95mm, Lead Span 2.8mm, IPC Medium Density)
footprint SOT23-5_L (SOT23, 5-Leads, Body 2.9x1.6mm, Pitch 0.95mm, Lead Span 2.8mm, IPC High Density)
footprint SOT23-5_M (SOT23, 5-Leads, Body 2.9x1.6mm, Pitch 0.95mm, Lead Span 2.8mm, IPC Low Density)
pins: 1 ~{RST} (out), 2 GND (power), 3 ~{MR} (in), 4 RST IN (in), 5 VCC (power)

## MAX6309UK29D1-T
designator U?
5-Pin, Multiple-Input, Programmable Reset IC
footprint SOT23-5_N (SOT23, 5-Leads, Body 2.9x1.6mm, Pitch 0.95mm, Lead Span 2.8mm, IPC Medium Density)
footprint SOT23-5_L (SOT23, 5-Leads, Body 2.9x1.6mm, Pitch 0.95mm, Lead Span 2.8mm, IPC High Density)
footprint SOT23-5_M (SOT23, 5-Leads, Body 2.9x1.6mm, Pitch 0.95mm, Lead Span 2.8mm, IPC Low Density)
pins: 1 ~{RST} (out), 2 GND (power), 3 ~{MR} (in), 4 RST IN (in), 5 VCC (power)

## MAX6309UK29D2-T
designator U?
5-Pin, Multiple-Input, Programmable Reset IC
footprint SOT23-5_N (SOT23, 5-Leads, Body 2.9x1.6mm, Pitch 0.95mm, Lead Span 2.8mm, IPC Medium Density)
footprint SOT23-5_L (SOT23, 5-Leads, Body 2.9x1.6mm, Pitch 0.95mm, Lead Span 2.8mm, IPC High Density)
footprint SOT23-5_M (SOT23, 5-Leads, Body 2.9x1.6mm, Pitch 0.95mm, Lead Span 2.8mm, IPC Low Density)
pins: 1 ~{RST} (out), 2 GND (power), 3 ~{MR} (in), 4 RST IN (in), 5 VCC (power)

## MAX6309UK29D3-T
designator U?
5-Pin, Multiple-Input, Programmable Reset IC
footprint SOT23-5_N (SOT23, 5-Leads, Body 2.9x1.6mm, Pitch 0.95mm, Lead Span 2.8mm, IPC Medium Density)
footprint SOT23-5_L (SOT23, 5-Leads, Body 2.9x1.6mm, Pitch 0.95mm, Lead Span 2.8mm, IPC High Density)
footprint SOT23-5_M (SOT23, 5-Leads, Body 2.9x1.6mm, Pitch 0.95mm, Lead Span 2.8mm, IPC Low Density)
pins: 1 ~{RST} (out), 2 GND (power), 3 ~{MR} (in), 4 RST IN (in), 5 VCC (power)

## MAX6309UK29D4-T
designator U?
5-Pin, Multiple-Input, Programmable Reset IC
footprint SOT23-5_N (SOT23, 5-Leads, Body 2.9x1.6mm, Pitch 0.95mm, Lead Span 2.8mm, IPC Medium Density)
footprint SOT23-5_L (SOT23, 5-Leads, Body 2.9x1.6mm, Pitch 0.95mm, Lead Span 2.8mm, IPC High Density)
footprint SOT23-5_M (SOT23, 5-Leads, Body 2.9x1.6mm, Pitch 0.95mm, Lead Span 2.8mm, IPC Low Density)
pins: 1 ~{RST} (out), 2 GND (power), 3 ~{MR} (in), 4 RST IN (in), 5 VCC (power)

## MAX6309UK30D1-T
designator U?
5-Pin, Multiple-Input, Programmable Reset IC
footprint SOT23-5_N (SOT23, 5-Leads, Body 2.9x1.6mm, Pitch 0.95mm, Lead Span 2.8mm, IPC Medium Density)
footprint SOT23-5_L (SOT23, 5-Leads, Body 2.9x1.6mm, Pitch 0.95mm, Lead Span 2.8mm, IPC High Density)
footprint SOT23-5_M (SOT23, 5-Leads, Body 2.9x1.6mm, Pitch 0.95mm, Lead Span 2.8mm, IPC Low Density)
pins: 1 ~{RST} (out), 2 GND (power), 3 ~{MR} (in), 4 RST IN (in), 5 VCC (power)

## MAX6309UK30D2-T
designator U?
5-Pin, Multiple-Input, Programmable Reset IC
footprint SOT23-5_N (SOT23, 5-Leads, Body 2.9x1.6mm, Pitch 0.95mm, Lead Span 2.8mm, IPC Medium Density)
footprint SOT23-5_L (SOT23, 5-Leads, Body 2.9x1.6mm, Pitch 0.95mm, Lead Span 2.8mm, IPC High Density)
footprint SOT23-5_M (SOT23, 5-Leads, Body 2.9x1.6mm, Pitch 0.95mm, Lead Span 2.8mm, IPC Low Density)
pins: 1 ~{RST} (out), 2 GND (power), 3 ~{MR} (in), 4 RST IN (in), 5 VCC (power)

## MAX6309UK30D3-T
designator U?
5-Pin, Multiple-Input, Programmable Reset IC
footprint SOT23-5_N (SOT23, 5-Leads, Body 2.9x1.6mm, Pitch 0.95mm, Lead Span 2.8mm, IPC Medium Density)
footprint SOT23-5_L (SOT23, 5-Leads, Body 2.9x1.6mm, Pitch 0.95mm, Lead Span 2.8mm, IPC High Density)
footprint SOT23-5_M (SOT23, 5-Leads, Body 2.9x1.6mm, Pitch 0.95mm, Lead Span 2.8mm, IPC Low Density)
pins: 1 ~{RST} (out), 2 GND (power), 3 ~{MR} (in), 4 RST IN (in), 5 VCC (power)

## MAX6309UK30D4-T
designator U?
5-Pin, Multiple-Input, Programmable Reset IC
footprint SOT23-5_N (SOT23, 5-Leads, Body 2.9x1.6mm, Pitch 0.95mm, Lead Span 2.8mm, IPC Medium Density)
footprint SOT23-5_L (SOT23, 5-Leads, Body 2.9x1.6mm, Pitch 0.95mm, Lead Span 2.8mm, IPC High Density)
footprint SOT23-5_M (SOT23, 5-Leads, Body 2.9x1.6mm, Pitch 0.95mm, Lead Span 2.8mm, IPC Low Density)
pins: 1 ~{RST} (out), 2 GND (power), 3 ~{MR} (in), 4 RST IN (in), 5 VCC (power)

## MAX6309UK31D1-T
designator U?
5-Pin, Multiple-Input, Programmable Reset IC
footprint SOT23-5_N (SOT23, 5-Leads, Body 2.9x1.6mm, Pitch 0.95mm, Lead Span 2.8mm, IPC Medium Density)
footprint SOT23-5_L (SOT23, 5-Leads, Body 2.9x1.6mm, Pitch 0.95mm, Lead Span 2.8mm, IPC High Density)
footprint SOT23-5_M (SOT23, 5-Leads, Body 2.9x1.6mm, Pitch 0.95mm, Lead Span 2.8mm, IPC Low Density)
pins: 1 ~{RST} (out), 2 GND (power), 3 ~{MR} (in), 4 RST IN (in), 5 VCC (power)

## MAX6309UK31D2-T
designator U?
5-Pin, Multiple-Input, Programmable Reset IC
footprint SOT23-5_N (SOT23, 5-Leads, Body 2.9x1.6mm, Pitch 0.95mm, Lead Span 2.8mm, IPC Medium Density)
footprint SOT23-5_L (SOT23, 5-Leads, Body 2.9x1.6mm, Pitch 0.95mm, Lead Span 2.8mm, IPC High Density)
footprint SOT23-5_M (SOT23, 5-Leads, Body 2.9x1.6mm, Pitch 0.95mm, Lead Span 2.8mm, IPC Low Density)
pins: 1 ~{RST} (out), 2 GND (power), 3 ~{MR} (in), 4 RST IN (in), 5 VCC (power)

## MAX6309UK31D3-T
designator U?
5-Pin, Multiple-Input, Programmable Reset IC
footprint SOT23-5_N (SOT23, 5-Leads, Body 2.9x1.6mm, Pitch 0.95mm, Lead Span 2.8mm, IPC Medium Density)
footprint SOT23-5_L (SOT23, 5-Leads, Body 2.9x1.6mm, Pitch 0.95mm, Lead Span 2.8mm, IPC High Density)
footprint SOT23-5_M (SOT23, 5-Leads, Body 2.9x1.6mm, Pitch 0.95mm, Lead Span 2.8mm, IPC Low Density)
pins: 1 ~{RST} (out), 2 GND (power), 3 ~{MR} (in), 4 RST IN (in), 5 VCC (power)

## MAX6309UK31D4-T
designator U?
5-Pin, Multiple-Input, Programmable Reset IC
footprint SOT23-5_N (SOT23, 5-Leads, Body 2.9x1.6mm, Pitch 0.95mm, Lead Span 2.8mm, IPC Medium Density)
footprint SOT23-5_L (SOT23, 5-Leads, Body 2.9x1.6mm, Pitch 0.95mm, Lead Span 2.8mm, IPC High Density)
footprint SOT23-5_M (SOT23, 5-Leads, Body 2.9x1.6mm, Pitch 0.95mm, Lead Span 2.8mm, IPC Low Density)
pins: 1 ~{RST} (out), 2 GND (power), 3 ~{MR} (in), 4 RST IN (in), 5 VCC (power)

## MAX6309UK32D1-T
designator U?
5-Pin, Multiple-Input, Programmable Reset IC
footprint SOT23-5_N (SOT23, 5-Leads, Body 2.9x1.6mm, Pitch 0.95mm, Lead Span 2.8mm, IPC Medium Density)
footprint SOT23-5_L (SOT23, 5-Leads, Body 2.9x1.6mm, Pitch 0.95mm, Lead Span 2.8mm, IPC High Density)
footprint SOT23-5_M (SOT23, 5-Leads, Body 2.9x1.6mm, Pitch 0.95mm, Lead Span 2.8mm, IPC Low Density)
pins: 1 ~{RST} (out), 2 GND (power), 3 ~{MR} (in), 4 RST IN (in), 5 VCC (power)

## MAX6309UK32D2-T
designator U?
5-Pin, Multiple-Input, Programmable Reset IC
footprint SOT23-5_N (SOT23, 5-Leads, Body 2.9x1.6mm, Pitch 0.95mm, Lead Span 2.8mm, IPC Medium Density)
footprint SOT23-5_L (SOT23, 5-Leads, Body 2.9x1.6mm, Pitch 0.95mm, Lead Span 2.8mm, IPC High Density)
footprint SOT23-5_M (SOT23, 5-Leads, Body 2.9x1.6mm, Pitch 0.95mm, Lead Span 2.8mm, IPC Low Density)
pins: 1 ~{RST} (out), 2 GND (power), 3 ~{MR} (in), 4 RST IN (in), 5 VCC (power)

## MAX6309UK32D3-T
designator U?
5-Pin, Multiple-Input, Programmable Reset IC
footprint SOT23-5_N (SOT23, 5-Leads, Body 2.9x1.6mm, Pitch 0.95mm, Lead Span 2.8mm, IPC Medium Density)
footprint SOT23-5_L (SOT23, 5-Leads, Body 2.9x1.6mm, Pitch 0.95mm, Lead Span 2.8mm, IPC High Density)
footprint SOT23-5_M (SOT23, 5-Leads, Body 2.9x1.6mm, Pitch 0.95mm, Lead Span 2.8mm, IPC Low Density)
pins: 1 ~{RST} (out), 2 GND (power), 3 ~{MR} (in), 4 RST IN (in), 5 VCC (power)

## MAX6309UK32D4-T
designator U?
5-Pin, Multiple-Input, Programmable Reset IC
footprint SOT23-5_N (SOT23, 5-Leads, Body 2.9x1.6mm, Pitch 0.95mm, Lead Span 2.8mm, IPC Medium Density)
footprint SOT23-5_L (SOT23, 5-Leads, Body 2.9x1.6mm, Pitch 0.95mm, Lead Span 2.8mm, IPC High Density)
footprint SOT23-5_M (SOT23, 5-Leads, Body 2.9x1.6mm, Pitch 0.95mm, Lead Span 2.8mm, IPC Low Density)
pins: 1 ~{RST} (out), 2 GND (power), 3 ~{MR} (in), 4 RST IN (in), 5 VCC (power)

## MAX6309UK33D1-T
designator U?
5-Pin, Multiple-Input, Programmable Reset IC
footprint SOT23-5_N (SOT23, 5-Leads, Body 2.9x1.6mm, Pitch 0.95mm, Lead Span 2.8mm, IPC Medium Density)
footprint SOT23-5_L (SOT23, 5-Leads, Body 2.9x1.6mm, Pitch 0.95mm, Lead Span 2.8mm, IPC High Density)
footprint SOT23-5_M (SOT23, 5-Leads, Body 2.9x1.6mm, Pitch 0.95mm, Lead Span 2.8mm, IPC Low Density)
pins: 1 ~{RST} (out), 2 GND (power), 3 ~{MR} (in), 4 RST IN (in), 5 VCC (power)

## MAX6309UK33D2-T
designator U?
5-Pin, Multiple-Input, Programmable Reset IC
footprint SOT23-5_N (SOT23, 5-Leads, Body 2.9x1.6mm, Pitch 0.95mm, Lead Span 2.8mm, IPC Medium Density)
footprint SOT23-5_L (SOT23, 5-Leads, Body 2.9x1.6mm, Pitch 0.95mm, Lead Span 2.8mm, IPC High Density)
footprint SOT23-5_M (SOT23, 5-Leads, Body 2.9x1.6mm, Pitch 0.95mm, Lead Span 2.8mm, IPC Low Density)
pins: 1 ~{RST} (out), 2 GND (power), 3 ~{MR} (in), 4 RST IN (in), 5 VCC (power)

## MAX6309UK33D3-T
designator U?
5-Pin, Multiple-Input, Programmable Reset IC
footprint SOT23-5_N (SOT23, 5-Leads, Body 2.9x1.6mm, Pitch 0.95mm, Lead Span 2.8mm, IPC Medium Density)
footprint SOT23-5_L (SOT23, 5-Leads, Body 2.9x1.6mm, Pitch 0.95mm, Lead Span 2.8mm, IPC High Density)
footprint SOT23-5_M (SOT23, 5-Leads, Body 2.9x1.6mm, Pitch 0.95mm, Lead Span 2.8mm, IPC Low Density)
pins: 1 ~{RST} (out), 2 GND (power), 3 ~{MR} (in), 4 RST IN (in), 5 VCC (power)

## MAX6309UK33D4-T
designator U?
5-Pin, Multiple-Input, Programmable Reset IC
footprint SOT23-5_N (SOT23, 5-Leads, Body 2.9x1.6mm, Pitch 0.95mm, Lead Span 2.8mm, IPC Medium Density)
footprint SOT23-5_L (SOT23, 5-Leads, Body 2.9x1.6mm, Pitch 0.95mm, Lead Span 2.8mm, IPC High Density)
footprint SOT23-5_M (SOT23, 5-Leads, Body 2.9x1.6mm, Pitch 0.95mm, Lead Span 2.8mm, IPC Low Density)
pins: 1 ~{RST} (out), 2 GND (power), 3 ~{MR} (in), 4 RST IN (in), 5 VCC (power)

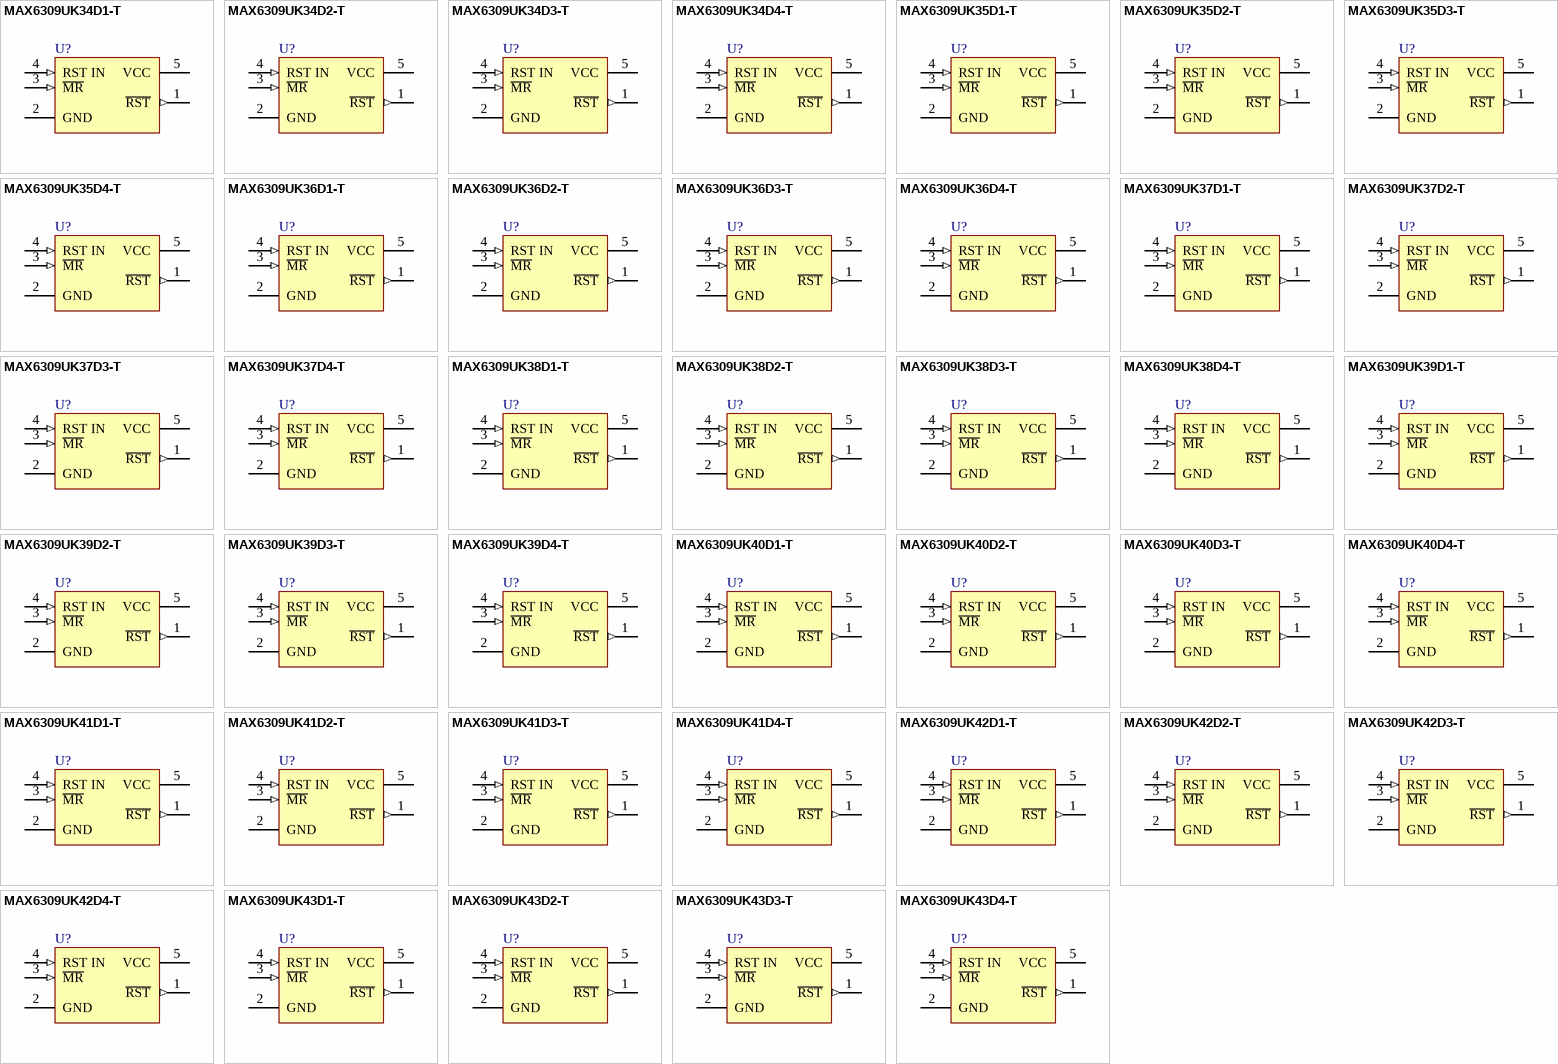
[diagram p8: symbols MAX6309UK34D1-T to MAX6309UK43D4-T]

## MAX6309UK34D1-T
designator U?
5-Pin, Multiple-Input, Programmable Reset IC
footprint SOT23-5_N (SOT23, 5-Leads, Body 2.9x1.6mm, Pitch 0.95mm, Lead Span 2.8mm, IPC Medium Density)
footprint SOT23-5_L (SOT23, 5-Leads, Body 2.9x1.6mm, Pitch 0.95mm, Lead Span 2.8mm, IPC High Density)
footprint SOT23-5_M (SOT23, 5-Leads, Body 2.9x1.6mm, Pitch 0.95mm, Lead Span 2.8mm, IPC Low Density)
pins: 1 ~{RST} (out), 2 GND (power), 3 ~{MR} (in), 4 RST IN (in), 5 VCC (power)

## MAX6309UK34D2-T
designator U?
5-Pin, Multiple-Input, Programmable Reset IC
footprint SOT23-5_N (SOT23, 5-Leads, Body 2.9x1.6mm, Pitch 0.95mm, Lead Span 2.8mm, IPC Medium Density)
footprint SOT23-5_L (SOT23, 5-Leads, Body 2.9x1.6mm, Pitch 0.95mm, Lead Span 2.8mm, IPC High Density)
footprint SOT23-5_M (SOT23, 5-Leads, Body 2.9x1.6mm, Pitch 0.95mm, Lead Span 2.8mm, IPC Low Density)
pins: 1 ~{RST} (out), 2 GND (power), 3 ~{MR} (in), 4 RST IN (in), 5 VCC (power)

## MAX6309UK34D3-T
designator U?
5-Pin, Multiple-Input, Programmable Reset IC
footprint SOT23-5_N (SOT23, 5-Leads, Body 2.9x1.6mm, Pitch 0.95mm, Lead Span 2.8mm, IPC Medium Density)
footprint SOT23-5_L (SOT23, 5-Leads, Body 2.9x1.6mm, Pitch 0.95mm, Lead Span 2.8mm, IPC High Density)
footprint SOT23-5_M (SOT23, 5-Leads, Body 2.9x1.6mm, Pitch 0.95mm, Lead Span 2.8mm, IPC Low Density)
pins: 1 ~{RST} (out), 2 GND (power), 3 ~{MR} (in), 4 RST IN (in), 5 VCC (power)

## MAX6309UK34D4-T
designator U?
5-Pin, Multiple-Input, Programmable Reset IC
footprint SOT23-5_N (SOT23, 5-Leads, Body 2.9x1.6mm, Pitch 0.95mm, Lead Span 2.8mm, IPC Medium Density)
footprint SOT23-5_L (SOT23, 5-Leads, Body 2.9x1.6mm, Pitch 0.95mm, Lead Span 2.8mm, IPC High Density)
footprint SOT23-5_M (SOT23, 5-Leads, Body 2.9x1.6mm, Pitch 0.95mm, Lead Span 2.8mm, IPC Low Density)
pins: 1 ~{RST} (out), 2 GND (power), 3 ~{MR} (in), 4 RST IN (in), 5 VCC (power)

## MAX6309UK35D1-T
designator U?
5-Pin, Multiple-Input, Programmable Reset IC
footprint SOT23-5_N (SOT23, 5-Leads, Body 2.9x1.6mm, Pitch 0.95mm, Lead Span 2.8mm, IPC Medium Density)
footprint SOT23-5_L (SOT23, 5-Leads, Body 2.9x1.6mm, Pitch 0.95mm, Lead Span 2.8mm, IPC High Density)
footprint SOT23-5_M (SOT23, 5-Leads, Body 2.9x1.6mm, Pitch 0.95mm, Lead Span 2.8mm, IPC Low Density)
pins: 1 ~{RST} (out), 2 GND (power), 3 ~{MR} (in), 4 RST IN (in), 5 VCC (power)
